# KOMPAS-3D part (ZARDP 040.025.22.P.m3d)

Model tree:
1. Плоскость XY
2. Плоскость ZX
3. Плоскость ZY
4. Ось X
5. Ось Y
6. Ось Z
7. Начало координат
8. Булева операция:1
9. Булева операция:2
10. Булева операция:3
11. Булева операция:4
